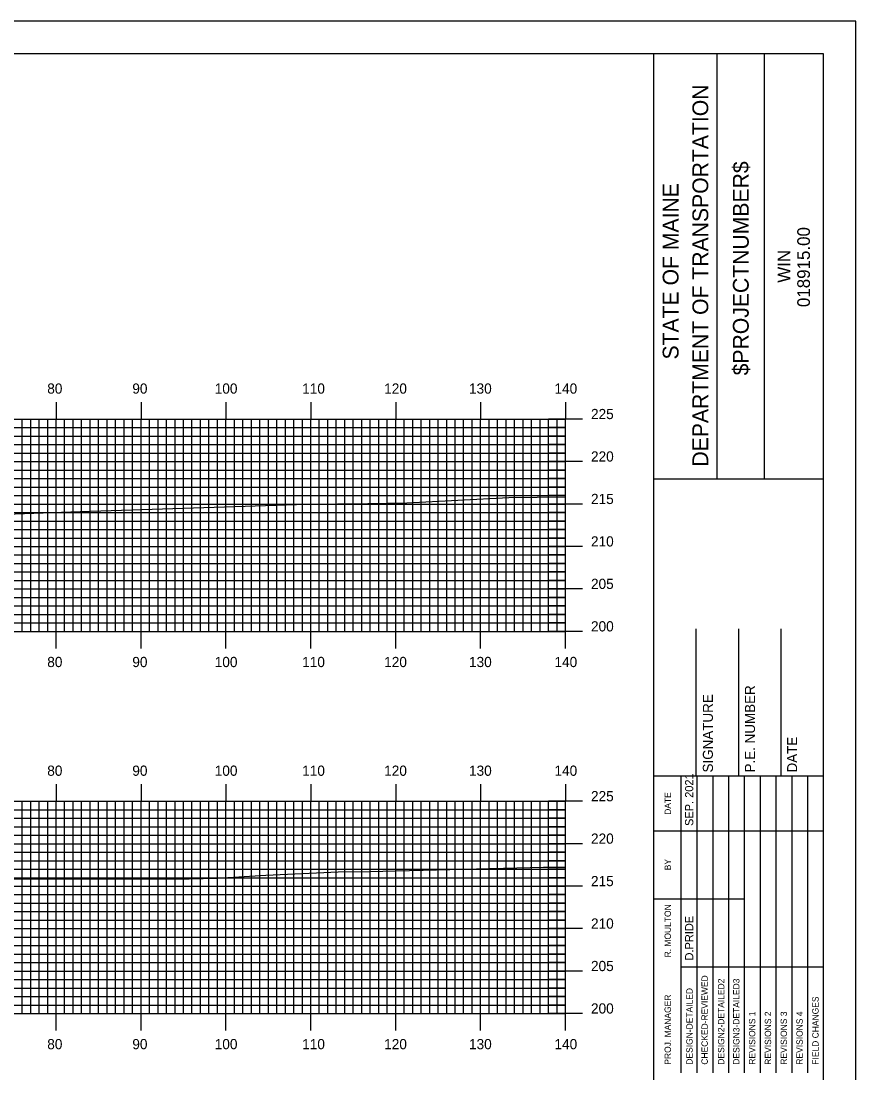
# Model space of a CAD drawing. Extents: x 1821211 to 1821555, y 442591 to 442811.
# Drawn here: x 1821453.1 to 1821551.4, y 442686.7 to 442810.5 of the extents above; entities that cross this region are included whole.
import ezdxf

# ---------------------------------------------------------------- set-up
doc = ezdxf.new("R2010")
doc.units = 0
for name, color, linetype in [('BORDER', 7, 'Continuous'), ('H_V ANNOTATION', 7, 'Continuous'), ('MAJOR', 7, 'Continuous'), ('MINOR', 7, 'Continuous'), ('PLOT BOUNDARY', 7, 'Continuous'), ('S_Roadway_Centerline', 7, 'Continuous')]:
    doc.layers.add(name, color=color, linetype=linetype)

msp = doc.modelspace()

# ---------------------------------------------------------------- linework, layer by layer
at = {"layer": 'BORDER'}
for p, q in [((1821527.63, 442596.67), (1821527.63, 442806.67)), ((1821535.09, 442756.66), (1821535.09, 442806.66)), ((1821540.68, 442756.66), (1821540.68, 442806.66)), ((1821527.63, 442756.65), (1821547.63, 442756.65)), ((1821532.63, 442721.67), (1821532.63, 442738.97)), ((1821537.63, 442721.67), (1821537.63, 442738.97)), ((1821542.63, 442721.67), (1821542.63, 442738.97)), ((1821527.63, 442721.67), (1821547.63, 442721.67))]:
    msp.add_line(p, q, dxfattribs=at)
msp.add_lwpolyline([(1821227.63, 442596.67), (1821547.63, 442596.67), (1821547.63, 442806.67), (1821227.63, 442806.67)], close=True, dxfattribs=at)
for points in [[(1821530.86, 442715.17), (1821530.86, 442721.67)], [(1821532.72, 442686.68), (1821532.72, 442721.67)], [(1821534.59, 442721.67), (1821534.59, 442686.68)], [(1821536.45, 442686.68), (1821536.45, 442721.67)], [(1821538.32, 442686.68), (1821538.32, 442721.67)], [(1821540.18, 442686.68), (1821540.18, 442721.67)], [(1821542.04, 442686.68), (1821542.04, 442721.67)], [(1821543.91, 442686.68), (1821543.91, 442721.67)], [(1821545.77, 442686.68), (1821545.77, 442721.67)], [(1821530.86, 442686.68), (1821530.86, 442720.26)], [(1821527.63, 442715.17), (1821547.63, 442715.17)], [(1821527.63, 442707.17), (1821530.86, 442707.17)], [(1821530.86, 442707.17), (1821538.31, 442707.17)], [(1821530.86, 442699.17), (1821547.63, 442699.17)]]:
    msp.add_lwpolyline(points, dxfattribs=at)
at = {"layer": 'MAJOR'}
for p, q in [((1821457.23, 442765.67), (1821457.23, 442763.67)), ((1821467.23, 442765.67), (1821467.23, 442763.67)), ((1821477.23, 442765.67), (1821477.23, 442763.67)), ((1821487.23, 442765.67), (1821487.23, 442763.67)), ((1821497.23, 442765.67), (1821497.23, 442763.67)), ((1821507.23, 442765.67), (1821507.23, 442763.67)), ((1821517.23, 442765.67), (1821517.23, 442763.67)), ((1821237.23, 442763.67), (1821517.23, 442763.67)), ((1821237.23, 442763.67), (1821517.23, 442763.67)), ((1821457.23, 442738.67), (1821457.23, 442763.67)), ((1821467.23, 442738.67), (1821467.23, 442763.67)), ((1821477.23, 442738.67), (1821477.23, 442763.67)), ((1821487.23, 442738.67), (1821487.23, 442763.67)), ((1821497.23, 442738.67), (1821497.23, 442763.67)), ((1821507.23, 442738.67), (1821507.23, 442763.67)), ((1821519.23, 442763.67), (1821515.23, 442763.67)), ((1821517.23, 442738.67), (1821517.23, 442763.67)), ((1821517.23, 442738.67), (1821517.23, 442763.67)), ((1821237.23, 442758.67), (1821517.23, 442758.67)), ((1821519.23, 442758.67), (1821515.23, 442758.67)), ((1821237.23, 442753.67), (1821517.23, 442753.67)), ((1821519.23, 442753.67), (1821515.23, 442753.67)), ((1821237.23, 442748.67), (1821517.23, 442748.67)), ((1821519.23, 442748.67), (1821515.23, 442748.67)), ((1821237.23, 442743.67), (1821517.23, 442743.67)), ((1821519.23, 442743.67), (1821515.23, 442743.67)), ((1821237.23, 442738.67), (1821517.23, 442738.67)), ((1821237.23, 442738.67), (1821517.23, 442738.67)), ((1821457.23, 442736.66), (1821457.23, 442738.67)), ((1821467.23, 442736.66), (1821467.23, 442738.67)), ((1821477.23, 442736.66), (1821477.23, 442738.67)), ((1821487.23, 442736.66), (1821487.23, 442738.67)), ((1821497.23, 442736.66), (1821497.23, 442738.67)), ((1821507.23, 442736.66), (1821507.23, 442738.67)), ((1821519.23, 442738.67), (1821515.23, 442738.67)), ((1821517.23, 442736.66), (1821517.23, 442738.67)), ((1821457.23, 442720.67), (1821457.23, 442718.67)), ((1821467.23, 442720.67), (1821467.23, 442718.67)), ((1821477.23, 442720.67), (1821477.23, 442718.67)), ((1821487.23, 442720.67), (1821487.23, 442718.67)), ((1821497.23, 442720.67), (1821497.23, 442718.67)), ((1821507.23, 442720.67), (1821507.23, 442718.67)), ((1821517.23, 442720.67), (1821517.23, 442718.67)), ((1821237.23, 442718.67), (1821517.23, 442718.67)), ((1821237.23, 442718.67), (1821517.23, 442718.67)), ((1821457.23, 442693.67), (1821457.23, 442718.67)), ((1821467.23, 442693.67), (1821467.23, 442718.67)), ((1821477.23, 442693.67), (1821477.23, 442718.67)), ((1821487.23, 442693.67), (1821487.23, 442718.67)), ((1821497.23, 442693.67), (1821497.23, 442718.67)), ((1821507.23, 442693.67), (1821507.23, 442718.67)), ((1821519.23, 442718.67), (1821515.23, 442718.67)), ((1821517.23, 442693.67), (1821517.23, 442718.67)), ((1821517.23, 442693.67), (1821517.23, 442718.67)), ((1821237.23, 442713.67), (1821517.23, 442713.67)), ((1821519.23, 442713.67), (1821515.23, 442713.67)), ((1821237.23, 442708.67), (1821517.23, 442708.67)), ((1821519.23, 442708.67), (1821515.23, 442708.67)), ((1821237.23, 442703.67), (1821517.23, 442703.67)), ((1821519.23, 442703.67), (1821515.23, 442703.67)), ((1821237.23, 442698.67), (1821517.23, 442698.67)), ((1821519.23, 442698.67), (1821515.23, 442698.67)), ((1821237.23, 442693.67), (1821517.23, 442693.67)), ((1821237.23, 442693.67), (1821517.23, 442693.67)), ((1821457.23, 442691.66), (1821457.23, 442693.67)), ((1821467.23, 442691.66), (1821467.23, 442693.67)), ((1821477.23, 442691.66), (1821477.23, 442693.67)), ((1821487.23, 442691.66), (1821487.23, 442693.67)), ((1821497.23, 442691.66), (1821497.23, 442693.67)), ((1821507.23, 442691.66), (1821507.23, 442693.67)), ((1821519.23, 442693.67), (1821515.23, 442693.67)), ((1821517.23, 442691.66), (1821517.23, 442693.67))]:
    msp.add_line(p, q, dxfattribs=at)
at = {"layer": 'MINOR'}
for p, q in [((1821453.23, 442738.67), (1821453.23, 442763.67)), ((1821454.23, 442738.67), (1821454.23, 442763.67)), ((1821455.23, 442738.67), (1821455.23, 442763.67)), ((1821456.23, 442738.67), (1821456.23, 442763.67)), ((1821458.23, 442738.67), (1821458.23, 442763.67)), ((1821459.23, 442738.67), (1821459.23, 442763.67)), ((1821460.23, 442738.67), (1821460.23, 442763.67)), ((1821461.23, 442738.67), (1821461.23, 442763.67)), ((1821462.23, 442738.67), (1821462.23, 442763.67)), ((1821463.23, 442738.67), (1821463.23, 442763.67)), ((1821464.23, 442738.67), (1821464.23, 442763.67)), ((1821465.23, 442738.67), (1821465.23, 442763.67)), ((1821466.23, 442738.67), (1821466.23, 442763.67)), ((1821468.23, 442738.67), (1821468.23, 442763.67)), ((1821469.23, 442738.67), (1821469.23, 442763.67)), ((1821470.23, 442738.67), (1821470.23, 442763.67)), ((1821471.23, 442738.67), (1821471.23, 442763.67)), ((1821472.23, 442738.67), (1821472.23, 442763.67)), ((1821473.23, 442738.67), (1821473.23, 442763.67)), ((1821474.23, 442738.67), (1821474.23, 442763.67)), ((1821475.23, 442738.67), (1821475.23, 442763.67)), ((1821476.23, 442738.67), (1821476.23, 442763.67)), ((1821478.23, 442738.67), (1821478.23, 442763.67)), ((1821479.23, 442738.67), (1821479.23, 442763.67)), ((1821480.23, 442738.67), (1821480.23, 442763.67)), ((1821481.23, 442738.67), (1821481.23, 442763.67)), ((1821482.23, 442738.67), (1821482.23, 442763.67)), ((1821483.23, 442738.67), (1821483.23, 442763.67)), ((1821484.23, 442738.67), (1821484.23, 442763.67)), ((1821485.23, 442738.67), (1821485.23, 442763.67)), ((1821486.23, 442738.67), (1821486.23, 442763.67)), ((1821488.23, 442738.67), (1821488.23, 442763.67)), ((1821489.23, 442738.67), (1821489.23, 442763.67)), ((1821490.23, 442738.67), (1821490.23, 442763.67)), ((1821491.23, 442738.67), (1821491.23, 442763.67)), ((1821492.23, 442738.67), (1821492.23, 442763.67)), ((1821493.23, 442738.67), (1821493.23, 442763.67)), ((1821494.23, 442738.67), (1821494.23, 442763.67)), ((1821495.23, 442738.67), (1821495.23, 442763.67)), ((1821496.23, 442738.67), (1821496.23, 442763.67)), ((1821498.23, 442738.67), (1821498.23, 442763.67)), ((1821499.23, 442738.67), (1821499.23, 442763.67)), ((1821500.23, 442738.67), (1821500.23, 442763.67)), ((1821501.23, 442738.67), (1821501.23, 442763.67)), ((1821502.23, 442738.67), (1821502.23, 442763.67)), ((1821503.23, 442738.67), (1821503.23, 442763.67)), ((1821504.23, 442738.67), (1821504.23, 442763.67)), ((1821505.23, 442738.67), (1821505.23, 442763.67)), ((1821506.23, 442738.67), (1821506.23, 442763.67)), ((1821508.23, 442738.67), (1821508.23, 442763.67)), ((1821509.23, 442738.67), (1821509.23, 442763.67)), ((1821510.23, 442738.67), (1821510.23, 442763.67)), ((1821511.23, 442738.67), (1821511.23, 442763.67)), ((1821512.23, 442738.67), (1821512.23, 442763.67)), ((1821513.23, 442738.67), (1821513.23, 442763.67)), ((1821514.23, 442738.67), (1821514.23, 442763.67)), ((1821515.23, 442738.67), (1821515.23, 442763.67)), ((1821516.23, 442738.67), (1821516.23, 442763.67)), ((1821237.23, 442762.67), (1821517.23, 442762.67)), ((1821517.23, 442762.67), (1821515.23, 442762.67)), ((1821237.23, 442761.67), (1821517.23, 442761.67)), ((1821517.23, 442761.67), (1821515.23, 442761.67)), ((1821237.23, 442760.67), (1821517.23, 442760.67)), ((1821517.23, 442760.67), (1821515.23, 442760.67)), ((1821237.23, 442759.67), (1821517.23, 442759.67)), ((1821517.23, 442759.67), (1821515.23, 442759.67)), ((1821237.23, 442757.67), (1821517.23, 442757.67)), ((1821517.23, 442757.67), (1821515.23, 442757.67)), ((1821237.23, 442756.67), (1821517.23, 442756.67)), ((1821517.23, 442756.67), (1821515.23, 442756.67)), ((1821237.23, 442755.67), (1821517.23, 442755.67)), ((1821517.23, 442755.67), (1821515.23, 442755.67)), ((1821237.23, 442754.67), (1821517.23, 442754.67)), ((1821517.23, 442754.67), (1821515.23, 442754.67)), ((1821237.23, 442752.67), (1821517.23, 442752.67)), ((1821517.23, 442752.67), (1821515.23, 442752.67)), ((1821237.23, 442751.67), (1821517.23, 442751.67)), ((1821517.23, 442751.67), (1821515.23, 442751.67)), ((1821237.23, 442750.67), (1821517.23, 442750.67)), ((1821517.23, 442750.67), (1821515.23, 442750.67)), ((1821237.23, 442749.67), (1821517.23, 442749.67)), ((1821517.23, 442749.67), (1821515.23, 442749.67)), ((1821237.23, 442747.67), (1821517.23, 442747.67)), ((1821517.23, 442747.67), (1821515.23, 442747.67)), ((1821237.23, 442746.67), (1821517.23, 442746.67)), ((1821517.23, 442746.67), (1821515.23, 442746.67)), ((1821237.23, 442745.67), (1821517.23, 442745.67)), ((1821517.23, 442745.67), (1821515.23, 442745.67)), ((1821237.23, 442744.67), (1821517.23, 442744.67)), ((1821517.23, 442744.67), (1821515.23, 442744.67)), ((1821237.23, 442742.67), (1821517.23, 442742.67)), ((1821517.23, 442742.67), (1821515.23, 442742.67)), ((1821237.23, 442741.67), (1821517.23, 442741.67)), ((1821517.23, 442741.67), (1821515.23, 442741.67)), ((1821237.23, 442740.67), (1821517.23, 442740.67)), ((1821517.23, 442740.67), (1821515.23, 442740.67)), ((1821237.23, 442739.67), (1821517.23, 442739.67)), ((1821517.23, 442739.67), (1821515.23, 442739.67)), ((1821453.23, 442693.67), (1821453.23, 442718.67)), ((1821454.23, 442693.67), (1821454.23, 442718.67)), ((1821455.23, 442693.67), (1821455.23, 442718.67)), ((1821456.23, 442693.67), (1821456.23, 442718.67)), ((1821458.23, 442693.67), (1821458.23, 442718.67)), ((1821459.23, 442693.67), (1821459.23, 442718.67)), ((1821460.23, 442693.67), (1821460.23, 442718.67)), ((1821461.23, 442693.67), (1821461.23, 442718.67)), ((1821462.23, 442693.67), (1821462.23, 442718.67)), ((1821463.23, 442693.67), (1821463.23, 442718.67)), ((1821464.23, 442693.67), (1821464.23, 442718.67)), ((1821465.23, 442693.67), (1821465.23, 442718.67)), ((1821466.23, 442693.67), (1821466.23, 442718.67)), ((1821468.23, 442693.67), (1821468.23, 442718.67)), ((1821469.23, 442693.67), (1821469.23, 442718.67)), ((1821470.23, 442693.67), (1821470.23, 442718.67)), ((1821471.23, 442693.67), (1821471.23, 442718.67)), ((1821472.23, 442693.67), (1821472.23, 442718.67)), ((1821473.23, 442693.67), (1821473.23, 442718.67)), ((1821474.23, 442693.67), (1821474.23, 442718.67)), ((1821475.23, 442693.67), (1821475.23, 442718.67)), ((1821476.23, 442693.67), (1821476.23, 442718.67)), ((1821478.23, 442693.67), (1821478.23, 442718.67)), ((1821479.23, 442693.67), (1821479.23, 442718.67)), ((1821480.23, 442693.67), (1821480.23, 442718.67)), ((1821481.23, 442693.67), (1821481.23, 442718.67)), ((1821482.23, 442693.67), (1821482.23, 442718.67)), ((1821483.23, 442693.67), (1821483.23, 442718.67)), ((1821484.23, 442693.67), (1821484.23, 442718.67)), ((1821485.23, 442693.67), (1821485.23, 442718.67)), ((1821486.23, 442693.67), (1821486.23, 442718.67)), ((1821488.23, 442693.67), (1821488.23, 442718.67)), ((1821489.23, 442693.67), (1821489.23, 442718.67)), ((1821490.23, 442693.67), (1821490.23, 442718.67)), ((1821491.23, 442693.67), (1821491.23, 442718.67)), ((1821492.23, 442693.67), (1821492.23, 442718.67)), ((1821493.23, 442693.67), (1821493.23, 442718.67)), ((1821494.23, 442693.67), (1821494.23, 442718.67)), ((1821495.23, 442693.67), (1821495.23, 442718.67)), ((1821496.23, 442693.67), (1821496.23, 442718.67)), ((1821498.23, 442693.67), (1821498.23, 442718.67)), ((1821499.23, 442693.67), (1821499.23, 442718.67)), ((1821500.23, 442693.67), (1821500.23, 442718.67)), ((1821501.23, 442693.67), (1821501.23, 442718.67)), ((1821502.23, 442693.67), (1821502.23, 442718.67)), ((1821503.23, 442693.67), (1821503.23, 442718.67)), ((1821504.23, 442693.67), (1821504.23, 442718.67)), ((1821505.23, 442693.67), (1821505.23, 442718.67)), ((1821506.23, 442693.67), (1821506.23, 442718.67)), ((1821508.23, 442693.67), (1821508.23, 442718.67)), ((1821509.23, 442693.67), (1821509.23, 442718.67)), ((1821510.23, 442693.67), (1821510.23, 442718.67)), ((1821511.23, 442693.67), (1821511.23, 442718.67)), ((1821512.23, 442693.67), (1821512.23, 442718.67)), ((1821513.23, 442693.67), (1821513.23, 442718.67)), ((1821514.23, 442693.67), (1821514.23, 442718.67)), ((1821515.23, 442693.67), (1821515.23, 442718.67)), ((1821516.23, 442693.67), (1821516.23, 442718.67)), ((1821237.23, 442717.67), (1821517.23, 442717.67)), ((1821237.23, 442716.67), (1821517.23, 442716.67)), ((1821517.23, 442717.67), (1821515.23, 442717.67)), ((1821517.23, 442716.67), (1821515.23, 442716.67)), ((1821237.23, 442715.67), (1821517.23, 442715.67)), ((1821517.23, 442715.67), (1821515.23, 442715.67)), ((1821237.23, 442714.67), (1821517.23, 442714.67)), ((1821517.23, 442714.67), (1821515.23, 442714.67)), ((1821237.23, 442712.67), (1821517.23, 442712.67)), ((1821237.23, 442711.67), (1821517.23, 442711.67)), ((1821517.23, 442712.67), (1821515.23, 442712.67)), ((1821517.23, 442711.67), (1821515.23, 442711.67)), ((1821237.23, 442710.67), (1821517.23, 442710.67)), ((1821517.23, 442710.67), (1821515.23, 442710.67)), ((1821237.23, 442709.67), (1821517.23, 442709.67)), ((1821517.23, 442709.67), (1821515.23, 442709.67)), ((1821237.23, 442707.67), (1821517.23, 442707.67)), ((1821237.23, 442706.67), (1821517.23, 442706.67)), ((1821517.23, 442707.67), (1821515.23, 442707.67)), ((1821517.23, 442706.67), (1821515.23, 442706.67)), ((1821237.23, 442705.67), (1821517.23, 442705.67)), ((1821517.23, 442705.67), (1821515.23, 442705.67)), ((1821237.23, 442704.67), (1821517.23, 442704.67)), ((1821517.23, 442704.67), (1821515.23, 442704.67)), ((1821237.23, 442702.67), (1821517.23, 442702.67)), ((1821237.23, 442701.67), (1821517.23, 442701.67)), ((1821517.23, 442702.67), (1821515.23, 442702.67)), ((1821517.23, 442701.67), (1821515.23, 442701.67)), ((1821237.23, 442700.67), (1821517.23, 442700.67)), ((1821517.23, 442700.67), (1821515.23, 442700.67)), ((1821237.23, 442699.67), (1821517.23, 442699.67)), ((1821517.23, 442699.67), (1821515.23, 442699.67)), ((1821237.23, 442697.67), (1821517.23, 442697.67)), ((1821237.23, 442696.67), (1821517.23, 442696.67)), ((1821517.23, 442697.67), (1821515.23, 442697.67)), ((1821517.23, 442696.67), (1821515.23, 442696.67)), ((1821237.23, 442695.67), (1821517.23, 442695.67)), ((1821517.23, 442695.67), (1821515.23, 442695.67)), ((1821237.23, 442694.67), (1821517.23, 442694.67)), ((1821517.23, 442694.67), (1821515.23, 442694.67))]:
    msp.add_line(p, q, dxfattribs=at)
at = {"layer": 'PLOT BOUNDARY'}
msp.add_lwpolyline([(1821211.44, 442590.55), (1821551.44, 442590.55), (1821551.44, 442810.55), (1821211.44, 442810.55)], close=True, dxfattribs=at)
at = {"layer": 'S_Roadway_Centerline'}
for points in [[(1821325.17, 442749.23), (1821329.44, 442749.38), (1821340.71, 442749.42), (1821346.79, 442749.38), (1821362.22, 442749.65), (1821375.53, 442750.38), (1821379.82, 442750.56), (1821388.78, 442750.62), (1821409.08, 442751.15), (1821423.03, 442751.75), (1821426.49, 442751.84), (1821437.52, 442752.03), (1821440.35, 442752.09), (1821460.04, 442752.79), (1821486.75, 442753.64), (1821493.96, 442753.73), (1821498.54, 442753.82), (1821510.55, 442754.43), (1821517.23, 442754.51)], [(1821237.23, 442703.27), (1821237.53, 442703.28), (1821264.33, 442703.79), (1821303.65, 442705.19), (1821311.23, 442705.53), (1821321.49, 442705.86), (1821351.91, 442706.32), (1821353.94, 442706.35), (1821354.59, 442706.37), (1821355.88, 442706.42), (1821388.83, 442707.87), (1821420.29, 442709.25), (1821422.31, 442709.32), (1821426.24, 442709.4), (1821439.35, 442709.51), (1821465.23, 442709.52), (1821471.24, 442709.51), (1821476.19, 442709.63), (1821481.91, 442709.95), (1821490.45, 442710.34), (1821494.15, 442710.38), (1821514.65, 442710.89), (1821517.23, 442710.91)]]:
    msp.add_lwpolyline(points, dxfattribs=at)

# ---------------------------------------------------------------- texts
at = {"layer": 'BORDER'}
for s, height, p in [('DEPARTMENT OF TRANSPORTATION', 1.8635, (1821534.04, 442758.08)), ('$PROJECTNUMBER$', 1.8635, (1821538.81, 442768.82)), ('STATE OF MAINE', 1.8635, (1821530.54, 442770.69)), ('018915.00', 1.491, (1821546.02, 442776.86)), ('WIN', 1.491, (1821543.7, 442779.73)), ('P.E. NUMBER', 1.1811, (1821539.55, 442722.06)), ('SIGNATURE', 1.181, (1821534.59, 442722.06)), ('DATE', 1.181, (1821544.51, 442722.06)), ('SEP. 2021', 0.969, (1821532.28, 442715.76)), ('DATE', 0.743, (1821529.64, 442717.08)), ('BY', 0.743, (1821529.64, 442710.54)), ('R. MOULTON', 0.745, (1821529.64, 442700.28)), ('D.PRIDE', 0.969, (1821532.28, 442699.92)), ('CHECKED-REVIEWED', 0.7455, (1821533.99, 442687.65)), ('DESIGN2-DETAILED2', 0.7455, (1821535.93, 442687.65)), ('DESIGN3-DETAILED3', 0.7455, (1821537.72, 442687.65)), ('PROJ. MANAGER', 0.7455, (1821529.64, 442687.65)), ('DESIGN-DETAILED', 0.7455, (1821532.2, 442687.65)), ('FIELD CHANGES', 0.7455, (1821547.04, 442687.65)), ('REVISIONS 1', 0.7455, (1821539.58, 442687.65)), ('REVISIONS 2', 0.7455, (1821541.45, 442687.65)), ('REVISIONS 3', 0.7455, (1821543.31, 442687.65)), ('REVISIONS 4', 0.7455, (1821545.17, 442687.65))]:
    msp.add_text(s, height=height, rotation=90, dxfattribs=at).set_placement(p)
at = {"layer": 'H_V ANNOTATION'}
for s, p in [('80', (1821456.18, 442766.67)), ('90', (1821466.2, 442766.67)), ('100', (1821475.91, 442766.67)), ('110', (1821486.21, 442766.67)), ('120', (1821495.87, 442766.67)), ('130', (1821505.86, 442766.67)), ('140', (1821515.93, 442766.67)), ('225', (1821520.23, 442763.67)), ('220', (1821520.23, 442758.67)), ('215', (1821520.23, 442753.67)), ('210', (1821520.23, 442748.67)), ('205', (1821520.23, 442743.67)), ('200', (1821520.23, 442738.67)), ('80', (1821456.18, 442734.47)), ('90', (1821466.2, 442734.47)), ('100', (1821475.91, 442734.47)), ('110', (1821486.21, 442734.47)), ('120', (1821495.87, 442734.47)), ('130', (1821505.86, 442734.47)), ('140', (1821515.93, 442734.47)), ('80', (1821456.18, 442721.67)), ('90', (1821466.2, 442721.67)), ('100', (1821475.91, 442721.67)), ('110', (1821486.21, 442721.67)), ('120', (1821495.87, 442721.67)), ('130', (1821505.86, 442721.67)), ('140', (1821515.93, 442721.67)), ('225', (1821520.23, 442718.67)), ('220', (1821520.23, 442713.67)), ('215', (1821520.23, 442708.67)), ('210', (1821520.23, 442703.67)), ('205', (1821520.23, 442698.67)), ('200', (1821520.23, 442693.67)), ('80', (1821456.18, 442689.47)), ('90', (1821466.2, 442689.47)), ('100', (1821475.91, 442689.47)), ('110', (1821486.21, 442689.47)), ('120', (1821495.87, 442689.47)), ('130', (1821505.86, 442689.47)), ('140', (1821515.93, 442689.47))]:
    msp.add_text(s, height=1.2, dxfattribs=at).set_placement(p)

doc.saveas('drawing.dxf')
